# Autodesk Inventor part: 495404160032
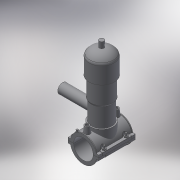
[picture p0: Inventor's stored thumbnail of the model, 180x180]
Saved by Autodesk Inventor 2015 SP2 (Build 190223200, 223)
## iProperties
Created: 2017-07
Part Number: 495404160032
Material: Generic
Description: PLASSON TAPPING VALVE 160-32
Document SubType Name: Modeling
Designer: KIM
Density: 1 g/cm^3
Appearance: Default
Author: KIM
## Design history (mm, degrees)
derived "495404-4954S4.ipt"
feature "Solid1::495404-4954S4.ipt"
feature "Solid2::495404-4954S4.ipt"
tag "TaggingFeature1"
body "Solid1"
body "Solid2"
other parameters: "d2" = 202, "d4" = 118, "d5" = 0, "d6" = 0.1, "d8" = 0, "d19" = 6, "d20" = 6, "d21" = 70.8, "d23" = 0, "d24" = 35.4, "d26" = 0, "d27" = 3, "d28" = 3, "d29" = 3, "d30" = 53.33333, "d31" = 6, "d32" = 0, "d33" = 0, "d34" = 0.6, "d40" = 99.84, "d47" = 142, "d70" = 15, "d72" = 0, "d73" = 6, "d75" = 5, "d76" = 0, "d77" = 8, "d79" = 15, "d80" = 47.2, "d82" = 5 deg, "d84" = 4, "d85" = 14, "d86" = 0, "d87" = 3, "d88" = 0, "d89" = 1, "d90" = 1, "d91" = 94.4, "d92" = 0, "d93" = 0.5, "d94" = 84.21053, "d96" = 197.76, "d97" = 2.36, "d98" = 0, "d120" = 140 deg, "d121" = 24.228, "d122" = 20 deg, "d123" = 384, "d124" = 115.2, "d126" = 0, "d143" = 164.8, "d145" = 24.61538, "d149" = 2.4, "d150" = 27.07692, "d153" = 118, "d154" = 0, "d156" = 96, "d157" = 160 deg, "d159" = 6.4, "d161" = 2.4, "d162" = 70.8, "d163" = 0, "d167" = 16, "d168" = 93.65854, "d170" = 3, "d172" = 0, "d173" = 1, "d176" = 20 deg, "d177" = 11.2, "d178" = 32, "d180" = 0, "d183" = 12.8, "d184" = 8.96, "d185" = 38.35, "d186" = 38.35, "d187" = 96, "d188" = 9.6, "d189" = 11.2, "d190" = 0, "d191" = 144, "d193" = 6.8, "d194" = 2.95, "d195" = 90 deg, "d197" = 0, "d199" = 0, "d205" = 14.64, "d206" = 81.33333, "d207" = 244, "d208" = 224.48, "d209" = 207.4, "d210" = 200.08, "d211" = 146.4, "d212" = 85.4, "d213" = 65.88, "d214" = 73.2, "d216" = 19.52, "d217" = 70.76, "d218" = 80.52, "d222" = 0, "d223" = 192, "d224" = 126, "d225" = 46, "d226" = 32, "d229" = 126, "d230" = 0, "B_" = 202, "H_" = 126, "L_" = 118, "d_t" = 6, "d_1" = 32, "H_1" = 46, "H_2" = 244, "d148" = 2.4, "d160" = 2.4, "d169" = 3, "d192" = 6.8, "d228" = 25.6
